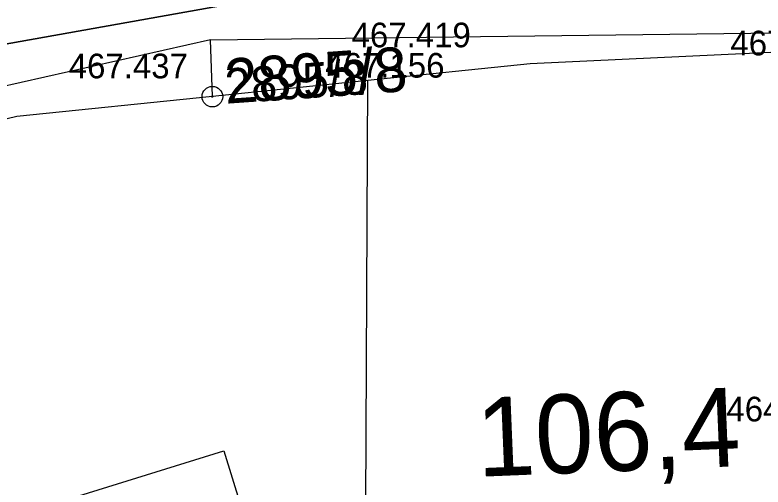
# Model space of a CAD drawing. Extents: x -758836 to -757729, y -1175316 to -1174366.
# Drawn here: x -758235.14 to -758198.73, y -1174798.73 to -1174775.74 of the extents above; entities that cross this region are included whole.
import ezdxf

# ---------------------------------------------------------------- set-up
doc = ezdxf.new("R2010")
doc.units = 0
for name, color, linetype in [('_NOR-popis', 7, 'Continuous'), ('_NOR-vytyčení', 7, 'Continuous'), ('G_Obvod stavby', 7, 'Continuous'), ('Hranice parcel', 7, 'Continuous'), ('Parcelní čísla', 7, 'Continuous'), ('Vrstva 61', 7, 'Continuous'), ('Značky bodu BP', 7, 'Continuous')]:
    doc.layers.add(name, color=color, linetype=linetype)

msp = doc.modelspace()

# ---------------------------------------------------------------- linework, layer by layer
at = {"layer": '_NOR-vytyčení'}
for p, q in [((-758282.298, -1174814.682), (-758224.972, -1174796.97)), ((-758224.972, -1174796.97), (-758213.164, -1174835.187))]:
    msp.add_line(p, q, dxfattribs=at)
at = {"layer": 'G_Obvod stavby'}
msp.add_lwpolyline([(-758392.72, -1174840.756), (-758391.23, -1174838.56), (-758368.37, -1174821.64), (-758340.31, -1174807.33), (-758320.27, -1174796.89), (-758301, -1174790.21), (-758267.96, -1174782.93), (-758224.96, -1174775.27), (-758184.87, -1174772.83), (-758142.71, -1174770.26), (-758089.84, -1174768.68), (-758106.02, -1174731.44), (-758149.09, -1174725.67), (-758199.62, -1174726.6), (-758225.76, -1174732.36), (-758252.17, -1174738.18), (-758254.97, -1174739.34), (-758266.58, -1174744.16), (-758279.45, -1174749.49), (-758302.42, -1174759.02), (-758331.68, -1174770.24), (-758367.17, -1174799.81), (-758405.64, -1174832.2)], dxfattribs=at)
at = {"layer": 'Hranice parcel'}
for p, q in [((-758225.62, -1174776.96), (-758198.02, -1174776.62)), ((-758225.62, -1174776.96), (-758263.57, -1174785.5)), ((-758225.53, -1174779.72), (-758225.62, -1174776.96)), ((-758217.96, -1174778.94), (-758225.53, -1174779.72)), ((-758218.18, -1174826.63), (-758217.96, -1174778.94))]:
    msp.add_line(p, q, dxfattribs=at)
for points in [[(-758184.87, -1174772.83), (-758224.96, -1174775.27), (-758267.96, -1174782.93), (-758301, -1174790.21), (-758320.27, -1174796.89)], [(-758198.02, -1174777.55), (-758210.07, -1174778.13), (-758217.96, -1174778.94)], [(-758225.53, -1174779.72), (-758235.04, -1174780.69), (-758238.83, -1174781.6)]]:
    msp.add_lwpolyline(points, dxfattribs=at)
at = {"layer": 'Značky bodu BP'}
for radius in [0.5, 0.0303]:
    msp.add_circle((-758225.53, -1174779.72), radius, dxfattribs=at)

# ---------------------------------------------------------------- texts
at = {"layer": '_NOR-popis'}
msp.add_text('106,4', height=3.8397, rotation=2.3427, dxfattribs=at).set_placement((-758212.612, -1174798.231))
msp.add_text('106,4', height=3.8397, rotation=2.3427, dxfattribs=at).set_placement((-758212.612, -1174798.231))
at = {"layer": 'Parcelní čísla'}
for height in [2.1751, 1.7]:
    msp.add_text('2895/8', height=height, rotation=4, dxfattribs=at).set_placement((-758224.86, -1174780.067))
at = {"layer": 'Vrstva 61'}
for s, p in [('467.419', (-758218.755, -1174777.319)), ('467.079', (-758200.321, -1174777.712)), ('467.437', (-758232.522, -1174778.829)), ('467.156', (-758220.036, -1174778.795)), ('464.750', (-758200.517, -1174795.532))]:
    msp.add_text(s, height=1.2, dxfattribs=at).set_placement(p)

doc.saveas('drawing.dxf')
